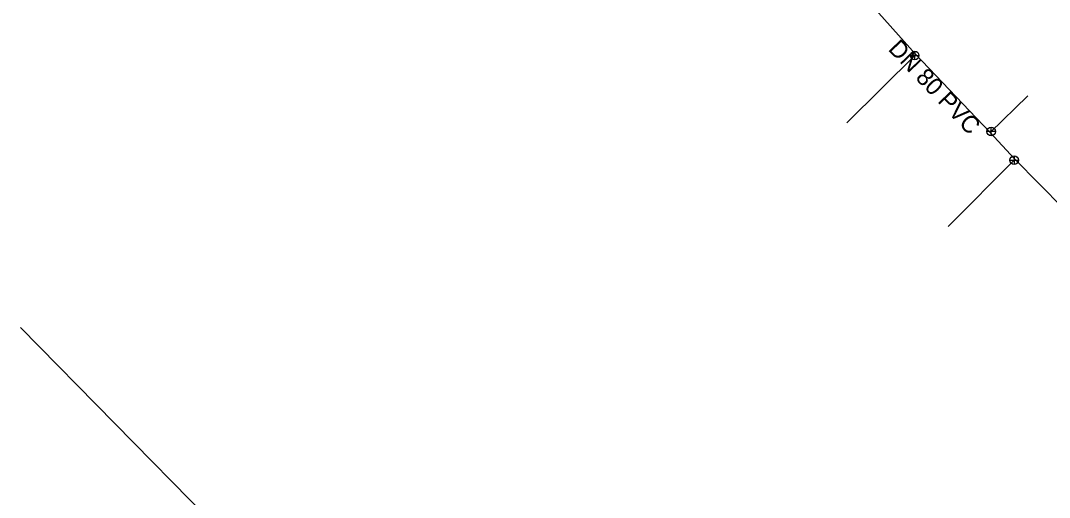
# Model space of a CAD drawing. Extents: x -446879 to -446633, y -1113504 to -1113264.
# Drawn here: x -446878.7 to -446782.8, y -1113382.1 to -1113337.6 of the extents above; entities that cross this region are included whole.
import ezdxf

# ---------------------------------------------------------------- set-up
doc = ezdxf.new("R2010")
doc.units = 0
for name, color, linetype in [('_pripojka_priblizne_', 7, 'Continuous'), ('_voda_smvak_prevzato_z_dokumentace_', 7, 'Continuous'), ('Default', 7, 'Continuous'), ('MoLevel 46', 7, 'Continuous'), ('MoLevel 53', 7, 'Continuous')]:
    doc.layers.add(name, color=color, linetype=linetype)

# ---------------------------------------------------------------- blocks, each defined once
blk = doc.blocks.new('_uzaver_pripojka_')
at = {"layer": 'Default'}
for p, q in [((-0.000035, -0.000035), (0.000035, 0.000035)), ((0.000035, -0.000035), (-0.000035, 0.000035))]:
    blk.add_line(p, q, dxfattribs=at)
for radius in [0.00005, 0.0000025]:
    blk.add_circle((0, 0), radius, dxfattribs=at)

msp = doc.modelspace()

# ---------------------------------------------------------------- linework, layer by layer
at = {"layer": '_pripojka_priblizne_'}
for p, q in [((-446801.695, -1113347.151), (-446795.271, -1113340.8)), ((-446788.347, -1113348.064), (-446784.83, -1113344.643)), ((-446792.252, -1113356.812), (-446786.016, -1113350.564))]:
    msp.add_line(p, q, dxfattribs=at)
at = {"layer": '_voda_smvak_prevzato_z_dokumentace_'}
for points in [[(-446760.89, -1113377.1), (-446764.33, -1113373.76), (-446767.09, -1113370.6), (-446779.25, -1113357.44), (-446786.03, -1113350.55), (-446788.36, -1113348.05), (-446795.29, -1113340.78), (-446799.77, -1113335.76), (-446815.92, -1113318.89), (-446836.52, -1113297.01)], [(-446827.89, -1113418.6), (-446835.66, -1113410.34), (-446849.67, -1113395.89), (-446850.69, -1113394.88), (-446861.08, -1113384.12), (-446878.661, -1113366.242)]]:
    msp.add_lwpolyline(points, dxfattribs=at)

# ---------------------------------------------------------------- block references
at = {"layer": 'MoLevel 53'}
for p, xscale, yscale, rotation in [((-446795.37, -1113340.89), 7999.999999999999, 8000, -135.2168594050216), ((-446788.25, -1113347.97), 7999.999999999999, 7999.999999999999, 44.2120582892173), ((-446786.11, -1113350.65), 8000, 8000, -134.84299154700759)]:
    msp.add_blockref('_uzaver_pripojka_', p, dxfattribs=dict(at, xscale=xscale, yscale=yscale, rotation=rotation))

# ---------------------------------------------------------------- texts
at = {"layer": 'MoLevel 46'}
msp.add_text('DN 80 PVC', height=1.6049, rotation=313.62839, dxfattribs=at).set_placement((-446797.917, -1113340.351))

doc.saveas('drawing.dxf')
